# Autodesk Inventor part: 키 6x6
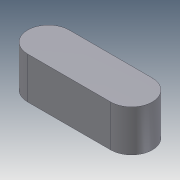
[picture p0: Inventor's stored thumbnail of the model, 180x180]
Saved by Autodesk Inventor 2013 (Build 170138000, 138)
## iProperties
Company: 한국ATC센터
Created: 2013-01
Part Number: 키 6x6
Document SubType Name: Modeling
Designer: KYOUNG IL JANG
Density: 7.25 g/cm^3
Material: 주철
Mass: 4.36193 g
Surface Area: 4.57646 cm^2
Volume: 0.601646 cm^3
Author: KYOUNG IL JANG
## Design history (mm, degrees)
sketch "스케치1"
  geometry: L1 (-6, -3)-(6, -3); L2 (6, 3)-(-6, 3); A1 r 3 centre (6, 0) between (6, -3) and (6, 3); A2 r 3 centre (-6, 0) between (-6, 3) and (-6, -3); 2 further points
  constraints: 4 end point, 4 point on circle, 4 tangent, 2 centre point, 1 horizontal, 1 horizontal alignment, 1 midpoint, 1 parallel, 1 vertical alignment
  dimensions: "d0" = 18 dimension on A1 A2; "d1" = 6 distance between parallel lines of L1 L2
extrude "돌출1" new body sketch "스케치1" stored distance "d2" = 6; taper "d3" = 0 deg
node "솔리드1"
